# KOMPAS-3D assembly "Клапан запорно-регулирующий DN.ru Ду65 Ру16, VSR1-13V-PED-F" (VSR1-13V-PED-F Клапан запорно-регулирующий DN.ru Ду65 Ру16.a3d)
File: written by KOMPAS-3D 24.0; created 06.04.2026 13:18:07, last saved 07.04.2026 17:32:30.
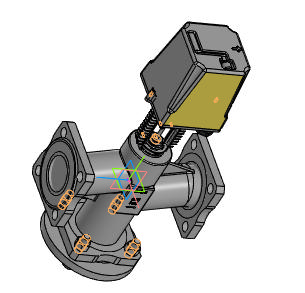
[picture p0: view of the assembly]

Document properties: Автор: R2D2; Полное имя файла: E:\Работа\Зайцев\Солянка\VSR1-13V-PED-F Клапан запорно-регулирующий DN.ru\DN65\исходные материалы\VSR1-13V-PED-F Клапан запорно-регулирующий DN.ru Ду65 Ру16.a3d

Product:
- Component [detail]: Фланец  | qty 2  | pos. 1  | Масса: 3.046076; Автор: R2D2; source file: Фланец.m3d
- Component [detail]: Фланец  | qty 1  | pos. 2  | Масса: 3.046076; Автор: R2D2; source file: Фланец.m3d
- Component [detail]: Корпус  | qty 1  | pos. 3  | Масса: 6.9; Автор: R2D2; source file: Корпус.m3d
- Component [detail]: Электропривод  | qty 1  | pos. 6  | Масса: 0.101125; Автор: R2D2; source file: Электропривод.m3d
- Component [standard]: Болт с шестигранной головкой ГОСТ Р ИСО 4014 - М16 x 65  | qty 4  | Материал: Не определено (density 1000 kg/m3); Масса: 0.1404; Раздел спецификации: Стандартные изделия; Рассекать на разрезах: no; additional columns: ГОСТ Р ИСО 4014-2013
- Component [standard]: Гайка М16-6H ГОСТ 5915-70  | qty 4  | Масса: 0.03761; Раздел спецификации: Стандартные изделия; Рассекать на разрезах: no; additional columns: М1,6-6H
- Part/product: Клапан запорно-регулирующий DN.ru Ду65 Ру16  | designation VSR1-13V-PED-F
    Масса: 17.2
    Раздел спецификации: Прочие изделия
    Примечание: D090-02892

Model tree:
1. Эскиз:1
2. Ось конической поверхности:19
3. Смещенная плоскость:19
4. ЛСК:19  (with: Плоскость XY, Плоскость ZX, Плоскость ZY, Ось X, Ось Y, Ось Z)
     Ось X. Y = -1; Ось Y. X = 1; Ось Z. Z = 1; Точка начала. Х = -51.2652; Точка начала. Y = -165; Точка начала. Z = -51.2652
5. Болтовое соединение
6. Массив по концентрической сетке:3  (with: Грань.Элемент выдавливания:1, Грань.Элемент вращения:1, Грань.Элемент выдавливания:8)  (4 pattern instances)
     Шаг 2 = 360; Ориентация = 2; Расстояние = -38

Expressions: VSR1-13V-PED-F; -L/2
Referenced files in E:\Работа\Зайцев\Солянка\VSR1-13V-PED-F Клапан запорно-регулирующий DN.ru\DN50\исходные материалы\: Фланец.m3d, Корпус.m3d, Электропривод.m3d
Referenced files in E:\Работа\Зайцев\Солянка\VSR1-13V-PED-F Клапан запорно-регулирующий DN.ru\DN65\исходные материалы\: Фланец.m3d, Корпус.m3d, Электропривод.m3d
Referenced files in C:\Program Files\ASCON\KOMPAS-3D v24\Libs\PolynomLib\DATA\vault\Methods\Kompas\3D\: PLib_Bolt_1_ISO_1100.m3d, PLib_Nut_OST92_900.m3d
Referenced files in E:\Работа\Зайцев\Солянка\VSR1-13V-PED-F Клапан запорно-регулирующий DN.ru\DN20\исходные материалы\: Фланец.m3d
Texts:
  Болт с шестигранной головкой
  Крепежное изделие ГОСТ
  Программные изделия  и базы данных
  Edge1
  Edge2
  TKR3D
  Справочник стандартных изделий
  Фланец (1)
  Фланец (2)
  Фланец (3)
  Болт с шестигранной головкой ГОСТ Р ИСО 4014 - М16 x 65 (1)
  hole1
  hole2
  bcut1
  hcut1
  cut1
  Плоскость XY.Начало координат
  Ось Z.Начало координат
  Плоскость ZY.Начало координат
  Плоскость ZX.Начало координат
  Ось Y.Начало координат
  Plane. Начало координат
